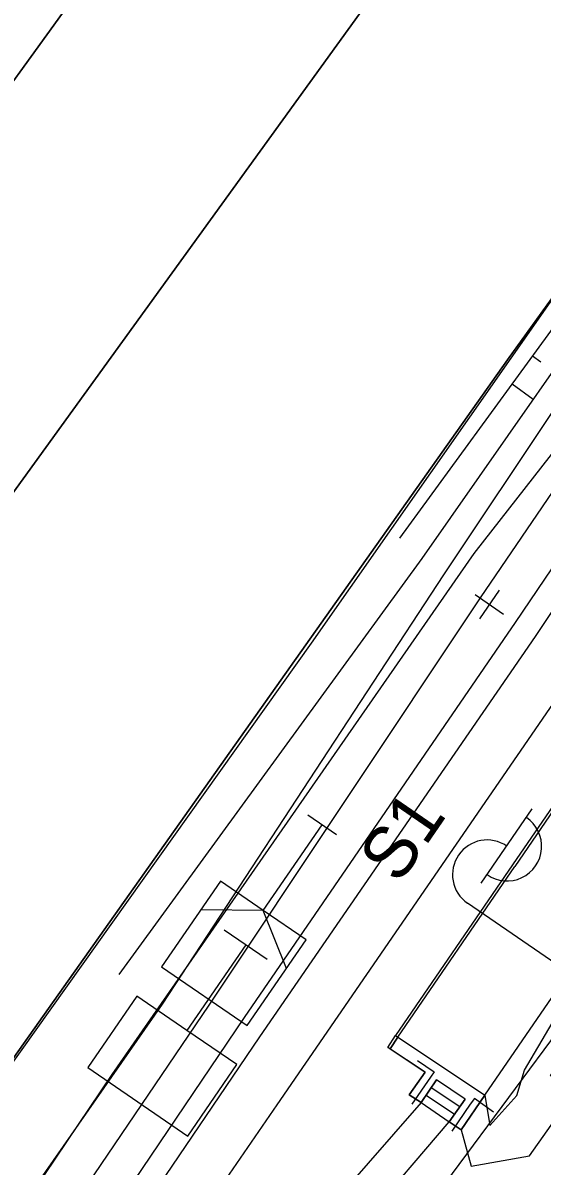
# Model space of a CAD drawing. Extents: x -558195 to -557985, y -1073457 to -1073198.
# Drawn here: x -558113.53 to -558098.53, y -1073355.93 to -1073322.92 of the extents above; entities that cross this region are included whole.
import ezdxf

# ---------------------------------------------------------------- set-up
doc = ezdxf.new("R2010")
doc.units = 0
for name, color, linetype in [('DWG-zabzař', 7, 'Continuous'), ('El2015-Elektro nadzemní', 7, 'Continuous'), ('El2015-Nástupiště', 7, 'Continuous'), ('El2015-Návěst místo trati', 7, 'Continuous'), ('El2015-Opěrná zeď - příkopa', 7, 'Continuous'), ('El2015-Plot - zábradlí', 7, 'Continuous'), ('El2015-Terén', 7, 'Continuous'), ('Kolej', 7, 'Continuous'), ('Komunikace', 7, 'Continuous'), ('Návěst místo trati', 7, 'Continuous'), ('Plot - zábradlí', 7, 'Continuous'), ('Přejezd - štěrkové lože', 7, 'Continuous'), ('Sonda - šrafa - vrstevnice', 7, 'Continuous'), ('Svazek obcí údolí Desné', 7, 'Continuous'), ('Svazek obcí-elektro', 7, 'Continuous'), ('Svazek obcí-zabezpečovací', 7, 'Continuous'), ('Terén', 7, 'Continuous'), ('Vrstva 15', 7, 'Continuous')]:
    doc.layers.add(name, color=color, linetype=linetype)

msp = doc.modelspace()

# ---------------------------------------------------------------- linework, layer by layer
at = {"layer": 'DWG-zabzař'}
for p, q in [((-558091.64, -1073326.89), (-558100.51, -1073338.24)), ((-558100.51, -1073338.24), (-558110.96, -1073353.29)), ((-558110.96, -1073353.29), (-558117.02, -1073362.28))]:
    msp.add_line(p, q, dxfattribs=at)
at = {"layer": 'El2015-Elektro nadzemní'}
for p, q in [((-558100.292, -1073347.764), (-558098.819, -1073345.621)), ((-558097.804, -1073350.323), (-558100.689, -1073348.34))]:
    msp.add_line(p, q, dxfattribs=at)
for centre, start, end in [((-558099.546, -1073346.699), 234.7979, 56.2031), ((-558100.122, -1073347.516), 55.5005, 235.5005)]:
    msp.add_arc(centre, 1, start, end, dxfattribs=at)
at = {"layer": 'El2015-Nástupiště'}
msp.add_line((-558102.702, -1073352.206), (-558099.322, -1073347.282), dxfattribs=at)
for points in [[(-558093.699, -1073338.955), (-558095.987, -1073342.272), (-558099.388, -1073347.237), (-558102.768, -1073352.161)], [(-558093.633, -1073339), (-558095.921, -1073342.317), (-558099.322, -1073347.282)], [(-558100.191, -1073353.885), (-558095.119, -1073346.503), (-558091.122, -1073340.69), (-558090.573, -1073339.885)]]:
    msp.add_lwpolyline(points, dxfattribs=at)
at = {"layer": 'El2015-Návěst místo trati'}
msp.add_line((-558106.475, -1073349.964), (-558107.711, -1073349.116), dxfattribs=at)
msp.add_lwpolyline([(-558107.093, -1073349.54), (-558108.791, -1073352.013), (-558110.234, -1073351.023), (-558111.648, -1073353.084), (-558108.763, -1073355.065), (-558107.348, -1073353.004), (-558108.791, -1073352.013)], dxfattribs=at)
at = {"layer": 'El2015-Opěrná zeď - příkopa'}
for p, q in [((-558102.918, -1073352.548), (-558102.702, -1073352.206)), ((-558101.916, -1073353.217), (-558101.916, -1073353.217)), ((-558101.736, -1073353.665), (-558100.907, -1073354.215)), ((-558102.372, -1073353.877), (-558102.372, -1073353.877)), ((-558101.884, -1073353.888), (-558101.061, -1073354.434)), ((-558100.753, -1073353.997), (-558101.215, -1073354.652)), ((-558100.875, -1073354.883), (-558100.191, -1073353.885)), ((-558101.215, -1073354.652), (-558101.215, -1073354.652))]:
    msp.add_line(p, q, dxfattribs=at)
for points in [[(-558102.768, -1073352.161), (-558100.191, -1073353.885), (-558100.875, -1073354.883), (-558101.215, -1073354.652), (-558100.753, -1073353.997), (-558101.588, -1073353.443), (-558102.025, -1073354.101), (-558102.372, -1073353.877), (-558101.916, -1073353.217), (-558102.986, -1073352.505), (-558102.768, -1073352.161)], [(-558102.768, -1073352.161), (-558102.702, -1073352.206), (-558102.702, -1073352.206), (-558102.918, -1073352.548)], [(-558102.986, -1073352.505), (-558102.918, -1073352.548), (-558102.918, -1073352.548), (-558101.916, -1073353.217), (-558102.372, -1073353.877), (-558102.025, -1073354.101), (-558101.215, -1073354.652), (-558100.875, -1073354.883), (-558100.875, -1073354.883)], [(-558102.025, -1073354.101), (-558102.025, -1073354.101), (-558101.588, -1073353.443)], [(-558101.588, -1073353.443), (-558102.025, -1073354.101), (-558101.215, -1073354.652), (-558100.753, -1073353.997), (-558101.588, -1073353.443)]]:
    msp.add_lwpolyline(points, dxfattribs=at)
at = {"layer": 'El2015-Plot - zábradlí'}
for points in [[(-558102.13, -1073352.882), (-558101.652, -1073353.211), (-558101.76, -1073353.365), (-558102.301, -1073354.149)], [(-558099.938, -1073354.372), (-558100.491, -1073353.98), (-558100.608, -1073354.141), (-558101.146, -1073354.928)]]:
    msp.add_lwpolyline(points, dxfattribs=at)
at = {"layer": 'El2015-Terén'}
for points in [[(-558100.191, -1073353.885), (-558100.042, -1073354.758), (-558099.266, -1073353.898), (-558099.045, -1073353.167), (-558098.244, -1073351.807), (-558097.213, -1073351.582), (-558090.522, -1073340.781)], [(-558100.875, -1073354.883), (-558100.587, -1073355.931), (-558098.897, -1073355.64), (-558097.764, -1073354.03), (-558098.294, -1073353.295), (-558097.774, -1073352.77), (-558096.662, -1073353.093), (-558089.38, -1073342.195)]]:
    msp.add_lwpolyline(points, dxfattribs=at)
at = {"layer": 'Kolej'}
msp.add_lwpolyline([(-558162.085, -1073435.464), (-558155.66, -1073426.127), (-558147.216, -1073413.854), (-558143.692, -1073408.727), (-558141.06, -1073404.904), (-558137.302, -1073399.438), (-558134.569, -1073395.461), (-558131.717, -1073391.307), (-558124.893, -1073381.375), (-558115.4, -1073367.564), (-558106.183, -1073354.164), (-558097.487, -1073341.511), (-558095.261, -1073338.268), (-558090.946, -1073331.927), (-558084.696, -1073322.399), (-558079.035, -1073313.091), (-558076.876, -1073309.237)], dxfattribs=at)
at = {"layer": 'Komunikace'}
msp.add_lwpolyline([(-558102.025, -1073354.101), (-558114.342, -1073368.192), (-558123.867, -1073381.998), (-558130.695, -1073391.932), (-558136.982, -1073401.101), (-558136.018, -1073401.785), (-558129.729, -1073392.612), (-558122.956, -1073382.764), (-558113.3, -1073368.807), (-558101.215, -1073354.652)], dxfattribs=at)
at = {"layer": 'Návěst místo trati'}
for p, q in [((-558099.645, -1073340.001), (-558100.469, -1073339.435)), ((-558099.774, -1073339.306), (-558100.34, -1073340.13)), ((-558104.475, -1073346.364), (-558105.299, -1073345.798)), ((-558106.586, -1073348.553), (-558104.887, -1073346.081))]:
    msp.add_line(p, q, dxfattribs=at)
for points in [[(-558106.586, -1073348.553), (-558107.822, -1073347.704), (-558109.522, -1073350.176), (-558107.049, -1073351.875), (-558105.35, -1073349.403), (-558106.586, -1073348.553)], [(-558105.917, -1073350.229), (-558106.586, -1073348.553), (-558108.39, -1073348.53)]]:
    msp.add_lwpolyline(points, dxfattribs=at)
at = {"layer": 'Plot - zábradlí'}
msp.add_lwpolyline([(-558081.585, -1073305.993), (-558081.958, -1073306.712), (-558085.995, -1073313.64), (-558091.417, -1073321.151), (-558105.2, -1073340.829), (-558131.731, -1073378.073), (-558133.048, -1073381.894), (-558138.367, -1073389.952)], dxfattribs=at)
at = {"layer": 'Přejezd - štěrkové lože'}
for points in [[(-558134.688, -1073392.469), (-558133.239, -1073389.979), (-558128.353, -1073382.563), (-558117.195, -1073366.537), (-558107.127, -1073351.64), (-558099.301, -1073340.237), (-558092.768, -1073330.583), (-558086.524, -1073321.182), (-558080.801, -1073311.959), (-558078.61, -1073308.043)], [(-558078.156, -1073308.355), (-558080.336, -1073312.26), (-558085.948, -1073321.555), (-558092.305, -1073330.965), (-558098.739, -1073340.644), (-558106.694, -1073352.203), (-558116.612, -1073366.808), (-558126.104, -1073380.52), (-558132.827, -1073390.228), (-558134.688, -1073392.469)]]:
    msp.add_lwpolyline(points, dxfattribs=at)
at = {"layer": 'Sonda - šrafa - vrstevnice'}
for p, q in [((-558098.808, -1073332.531), (-558098.571, -1073332.704)), ((-558099.397, -1073333.339), (-558098.79, -1073333.782))]:
    msp.add_line(p, q, dxfattribs=at)
at = {"layer": 'Svazek obcí údolí Desné'}
msp.add_lwpolyline([(-558167.537, -1073431.708), (-558157.08, -1073415.91), (-558144.45, -1073397.61), (-558143.83, -1073396.83), (-558140.29, -1073392.34), (-558139.67, -1073391.56), (-558138.4, -1073389.94), (-558132.32, -1073380.12), (-558131.71, -1073378.11), (-558099.53, -1073332.65), (-558091.21, -1073321.1), (-558086.89, -1073315.11), (-558086.02, -1073313.63), (-558082.18, -1073306.93), (-558081.607, -1073305.978)], dxfattribs=at)
at = {"layer": 'Svazek obcí-elektro'}
for p, q in [((-558100.292, -1073347.764), (-558098.819, -1073345.621)), ((-558097.804, -1073350.323), (-558100.689, -1073348.34))]:
    msp.add_line(p, q, dxfattribs=at)
msp.add_lwpolyline([(-558104.377, -1073360.537), (-558097.871, -1073351.756), (-558097.108, -1073350.87), (-558094.584, -1073347.94), (-558092.974, -1073346.202), (-558090.533, -1073342.919), (-558087.618, -1073340.975), (-558082.203, -1073333.171), (-558081.857, -1073332.87), (-558078.884, -1073336.019)], dxfattribs=at)
msp.add_lwpolyline([(-558104.377, -1073360.537), (-558097.871, -1073351.756), (-558097.108, -1073350.87), (-558094.584, -1073347.94), (-558092.974, -1073346.202), (-558090.533, -1073342.919), (-558087.618, -1073340.975), (-558082.203, -1073333.171), (-558081.857, -1073332.87), (-558078.884, -1073336.019)], dxfattribs=at)
for centre, start, end in [((-558099.546, -1073346.699), 234.7979, 56.2031), ((-558100.122, -1073347.516), 55.5005, 235.5005)]:
    msp.add_arc(centre, 1, start, end, dxfattribs=at)
at = {"layer": 'Svazek obcí-zabezpečovací'}
msp.add_lwpolyline([(-558104.377, -1073360.537), (-558097.871, -1073351.756), (-558094.584, -1073347.94), (-558092.974, -1073346.202), (-558090.533, -1073342.919), (-558087.618, -1073340.975), (-558082.203, -1073333.171), (-558081.697, -1073332.405), (-558081.138, -1073331.577), (-558080.334, -1073330.364), (-558074.513, -1073321.837)], dxfattribs=at)
at = {"layer": 'Terén'}
for points in [[(-558081.18, -1073306.272), (-558083.456, -1073310.395), (-558089.337, -1073319.304), (-558095.797, -1073328.403), (-558102.651, -1073337.801)], [(-558080.693, -1073306.608), (-558082.815, -1073310.544), (-558088.899, -1073319.675), (-558095.32, -1073328.817), (-558102.006, -1073338.385), (-558110.752, -1073350.405)], [(-558080.325, -1073306.861), (-558082.46, -1073310.779), (-558088.525, -1073319.94), (-558094.874, -1073329.104), (-558101.386, -1073338.86), (-558109.505, -1073351.261), (-558119.112, -1073365.018), (-558130.44, -1073381.204), (-558136.541, -1073389.319), (-558138.367, -1073389.952)], [(-558141.446, -1073388.086), (-558138.672, -1073391.073), (-558136.007, -1073391.106), (-558129.583, -1073381.786), (-558118.096, -1073365.959), (-558108.152, -1073351.289), (-558100.315, -1073339.526), (-558093.751, -1073329.892), (-558087.503, -1073320.498), (-558081.802, -1073311.451), (-558079.554, -1073307.392)]]:
    msp.add_lwpolyline(points, dxfattribs=at)
at = {"layer": 'Vrstva 15'}
for points in [[(-558167.537, -1073431.708), (-558157.08, -1073415.91), (-558144.45, -1073397.61), (-558143.83, -1073396.83), (-558140.29, -1073392.34), (-558139.67, -1073391.56), (-558138.4, -1073389.94), (-558132.32, -1073380.12), (-558131.71, -1073378.11), (-558099.53, -1073332.65), (-558091.21, -1073321.1), (-558086.89, -1073315.11), (-558086.02, -1073313.63), (-558082.18, -1073306.93), (-558081.607, -1073305.978)], [(-558128.354, -1073319.721), (-558124.37, -1073322.4), (-558121.16, -1073317.67), (-558119.85, -1073318.64), (-558115.48, -1073312.12), (-558113.01, -1073313.83), (-558110.09, -1073309.68), (-558108.58, -1073311.13), (-558106.1, -1073313.94), (-558146.53, -1073369.85), (-558151.628, -1073353.507)]]:
    msp.add_lwpolyline(points, dxfattribs=at)
for points in [[(-558139.67, -1073391.56), (-558140.9, -1073387.37), (-558143.89, -1073378.07), (-558101.27, -1073319.14), (-558106.1, -1073313.94), (-558108.58, -1073311.13), (-558110.09, -1073309.68), (-558108.61, -1073307.47), (-558103.03, -1073311.24), (-558100.91, -1073308.09), (-558098.7, -1073309.62), (-558100.86, -1073312.72), (-558101.25, -1073313.61), (-558091.21, -1073321.1), (-558099.53, -1073332.65), (-558131.71, -1073378.11), (-558132.32, -1073380.12), (-558138.4, -1073389.94)], [(-558143.89, -1073378.07), (-558146.53, -1073369.85), (-558106.1, -1073313.94), (-558101.27, -1073319.14)]]:
    msp.add_lwpolyline(points, close=True, dxfattribs=at)

# ---------------------------------------------------------------- texts
at = {"layer": 'El2015-Elektro nadzemní'}
msp.add_text('S1', height=1.5, rotation=55.5005, dxfattribs=at).set_placement((-558102.667, -1073347.831))
at = {"layer": 'Svazek obcí-elektro'}
msp.add_text('S1', height=1.5, rotation=55.5005, dxfattribs=at).set_placement((-558102.667, -1073347.831))

doc.saveas('drawing.dxf')
